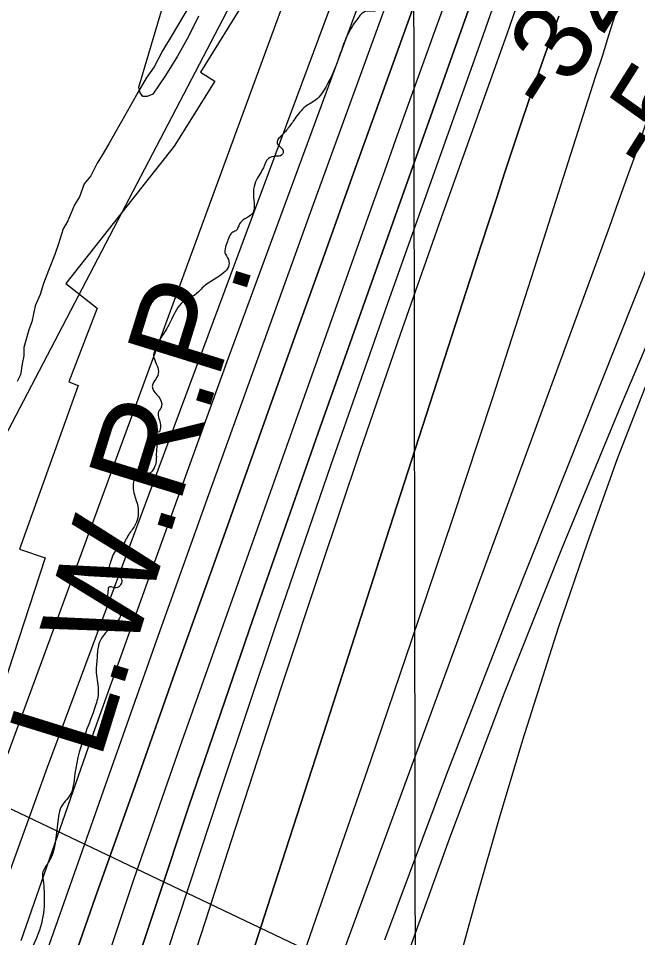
# Model space of a CAD drawing. Extents: x 3324104 to 3361979, y 612876 to 638273.
# Drawn here: x 3333142 to 3333670, y 619975 to 620759 of the extents above; entities that cross this region are included whole.
import ezdxf

# ---------------------------------------------------------------- set-up
doc = ezdxf.new("R2010")
doc.units = 0
for name, color, linetype in [('V-BORW-LINE', 7, 'Continuous'), ('V-GRID-MAJR', 7, 'Continuous'), ('V-RIVR-EDGE', 7, 'Continuous'), ('V-RIVR-RANG', 7, 'Continuous'), ('V-RRAP-RVMT', 7, 'Continuous'), ('V-SITE-VEGE', 7, 'Continuous'), ('V-TOPO-DPTH', 7, 'Continuous'), ('V-TOPO-MAJR', 7, 'Continuous'), ('V-TOPO-MINR', 7, 'Continuous'), ('V-TOPO-WATR', 7, 'Continuous'), ('V-TOPO-WATR-IDEN', 7, 'Continuous')]:
    doc.layers.add(name, color=color, linetype=linetype)

msp = doc.modelspace()

# ---------------------------------------------------------------- linework, layer by layer
at = {"layer": 'V-BORW-LINE'}
msp.add_spline([(3333279.31, 622009.12), (3333231.92, 621951.76), (3333205.11, 621897.16), (3333189.26, 621870.48), (3333179.51, 621841.77), (3333188.99, 621814.26), (3333211.1, 621772.38), (3333204.81, 621737.81), (3333188.63, 621719.97), (3333169, 621718.16), (3333123.21, 621708.41), (3333080.88, 621684.52), (3333055.17, 621653.52), (3333026.61, 621594.88), (3332950.24, 621540.71), (3332914.43, 621496.23), (3332875.47, 621420.15), (3332841.76, 621289.97), (3332823.69, 621156.25), (3332819.5, 621070.99), (3332810.28, 620972.6), (3332794.13, 620819.7), (3332773.59, 620648.76), (3332758.38, 620478.35), (3332763.01, 620333.58), (3332761.44, 620215.25), (3332749.59, 620090.1), (3332736.9, 620020.51), (3332757.48, 619884.42), (3332796.65, 619752.53), (3332836.81, 619685.21), (3332884.12, 619656.72), (3332907.36, 619782.97), (3332924.74, 619872.64), (3332933.46, 619955.31), (3332956.09, 620057.12), (3332961.28, 620162.95), (3332980.06, 620271.9), (3332986.08, 620455.32), (3332994.16, 620598.94), (3332995.81, 620645.82), (3333015.49, 620663.47), (3333033.59, 620670.41), (3333059.26, 620687.46), (3333079.42, 620760.33), (3333099.61, 620886.65), (3333120.36, 621062.97), (3333127.93, 621114.48), (3333147.58, 621275.48), (3333149.44, 621387.58), (3333160.45, 621495.69), (3333147.46, 621529.78), (3333165.68, 621561.99), (3333287.42, 621646.35), (3333352.56, 621666.03), (3333381.9, 621690.89), (3333384.67, 621754.99), (3333383.93, 621811), (3333402.75, 621857.49), (3333424.81, 621899.12), (3333503.16, 622012.37), (3333560.21, 622118.33), (3333589.92, 622173.14), (3333617.46, 622211.23), (3333650.61, 622258.29), (3333640.96, 622317.3), (3333564, 622281.97), (3333518.92, 622253.83), (3333446.06, 622201.36), (3333404.2, 622156.3), (3333335.5, 622066.47), (3333279.31, 622009.12)], degree=3, dxfattribs=at)
at = {"layer": 'V-GRID-MAJR'}
msp.add_spline([(3333482.84, 618266.12), (3333474.02, 624325.46), (3333465.21, 630386.73), (3333456.39, 636448.02), (3333456.39, 636449.93)], degree=3, dxfattribs=at)
at = {"layer": 'V-RIVR-EDGE'}
msp.add_spline([(3334928.97, 623567.85), (3334918.71, 623560.2), (3334914.68, 623556.19), (3334911.74, 623548.52), (3334903.31, 623541.96), (3334897.46, 623537.59), (3334883.89, 623523.37), (3334877.3, 623516.44), (3334875.1, 623512.79), (3334874.72, 623510.23), (3334869.21, 623497.09), (3334851.98, 623477.02), (3334839.87, 623459.87), (3334820.45, 623439.82), (3334813.49, 623432.89), (3334808.72, 623428.15), (3334791.86, 623408.45), (3334776.46, 623388.75), (3334766.19, 623376.71), (3334752.99, 623361.39), (3334747.86, 623355.19), (3334743.82, 623348.25), (3334740.89, 623343.87), (3334732.1, 623337.31), (3334728.8, 623334.4), (3334724.77, 623329.29), (3334712.3, 623315.07), (3334705.34, 623307.04), (3334701.67, 623300.47), (3334697.25, 623288.42), (3334692.47, 623279.29), (3334670.85, 623254.12), (3334652.51, 623232.23), (3334641.14, 623216.91), (3334634.54, 623206.32), (3334620.97, 623189.18), (3334601.16, 623162.54), (3334593.83, 623152.69), (3334582.08, 623132.98), (3334567.04, 623111.08), (3334554.2, 623092.11), (3334532.19, 623061.45), (3334516.05, 623038.46), (3334501.73, 623013.64), (3334486.32, 622989.92), (3334474.96, 622976.42), (3334471.29, 622971.31), (3334468.71, 622964.01), (3334466.11, 622945.37), (3334458.39, 622929.31), (3334449.59, 622916.9), (3334437.49, 622903.41), (3334430.89, 622897.21), (3334429.42, 622893.92), (3334430.51, 622889.17), (3334430.13, 622884.78), (3334422.09, 622884.44), (3334418.06, 622881.52), (3334414.39, 622876.78), (3334408.87, 622862.17), (3334399.7, 622849.03), (3334390.17, 622835.53), (3334378.44, 622826.06), (3334363.06, 622813.66), (3334337.75, 622777.9), (3334331.13, 622762.57), (3334327.81, 622750.15), (3334323.78, 622746.5), (3334319.75, 622741.39), (3334312.78, 622733), (3334306.55, 622727.54), (3334299.94, 622714.39), (3334295.53, 622705.63), (3334291.88, 622705.27), (3334287.48, 622702.36), (3334279.79, 622694.34), (3334261.06, 622661.85), (3334258.85, 622655.27), (3334258.48, 622650.52), (3334256.27, 622646.14), (3334249.67, 622637.39), (3334242.68, 622620.59), (3334233.12, 622595.39), (3334227.97, 622581.88), (3334227.22, 622574.2), (3334223.91, 622567.63), (3334219.88, 622563.62), (3334214.74, 622557.05), (3334213.27, 622550.47), (3334212.51, 622539.88), (3334211.02, 622528.55), (3334205.89, 622523.08), (3334199.67, 622521.63), (3334192.36, 622521.65), (3334181.38, 622517.65), (3334175.51, 622506.7), (3334173.65, 622495.01), (3334174.34, 622480.02), (3334173.22, 622468.69), (3334165.51, 622456.28), (3334156.34, 622440.95), (3334148.28, 622435.49), (3334140.95, 622428.56), (3334132.89, 622422.37), (3334131.79, 622417.62), (3334130.28, 622400.8), (3334129.53, 622392.03), (3334127.69, 622388.75), (3334124.76, 622384.73), (3334120.37, 622384.01), (3334113.42, 622383.67), (3334109.39, 622378.92), (3334105.72, 622372.72), (3334106.08, 622370.89), (3334106.8, 622364.67), (3334104.22, 622358.83), (3334092.86, 622346.07), (3334087.37, 622343.89), (3334077.85, 622335.14), (3334066.49, 622326.03), (3334058.79, 622317.64), (3334055.47, 622304.48), (3334054.73, 622298.64), (3334054.34, 622290.23), (3334052.14, 622286.22), (3334045.55, 622285.14), (3334038.59, 622277.84), (3334027.23, 622264.71), (3334003.75, 622232.6), (3333990.17, 622210.33), (3333969.97, 622172), (3333947.58, 622134.04), (3333931.07, 622108.49), (3333921.53, 622095.36), (3333906.11, 622069.44), (3333885.18, 622030.74), (3333866.11, 622004.11), (3333836.74, 621954.1), (3333808.83, 621904.82), (3333789, 621866.49), (3333773.55, 621825.22), (3333764.35, 621802.58), (3333753.68, 621773.36), (3333750.32, 621746.32), (3333745.51, 621722.57), (3333743.29, 621710.51), (3333742.49, 621684.19), (3333742.81, 621665.91), (3333738.03, 621655.69), (3333731.42, 621640.35), (3333723.35, 621629.41), (3333720.4, 621621.37), (3333716.71, 621607.86), (3333712.63, 621581.55), (3333709.64, 621557.06), (3333708.86, 621537.32), (3333711.36, 621514.29), (3333711.7, 621504.05), (3333710.95, 621494.55), (3333705.08, 621484.33), (3333691.48, 621455.48), (3333683.75, 621436.13), (3333680.79, 621419.32), (3333677.82, 621402.51), (3333676.69, 621386.8), (3333678.84, 621369.25), (3333684.3, 621359), (3333685.75, 621355.34), (3333683.92, 621353.88), (3333681.35, 621349.13), (3333676.95, 621343.66), (3333671.06, 621329.79), (3333664.81, 621313.35), (3333662.97, 621308.24), (3333659.66, 621300.57), (3333655.97, 621286.69), (3333654.86, 621280.11), (3333652.29, 621278.66), (3333646.07, 621275.38), (3333642.77, 621270.27), (3333641.29, 621264.43), (3333642.01, 621259.31), (3333642, 621253.09), (3333639.78, 621245.06), (3333636.12, 621240.68), (3333634.64, 621234.47), (3333623.99, 621213.66), (3333608.54, 621175.68), (3333598.59, 621144.27), (3333594.52, 621124.9), (3333593.41, 621119.42), (3333588.28, 621113.59), (3333583.51, 621106.65), (3333577.64, 621096.43), (3333573.24, 621092.79), (3333568.85, 621090.24), (3333567.74, 621085.49), (3333565.53, 621077.45), (3333558.92, 621067.96), (3333558.55, 621064.68), (3333561.45, 621054.07), (3333560.32, 621041.64), (3333556.27, 621029.59), (3333554.8, 621025.94), (3333558.8, 621018.62), (3333564.63, 621010.19), (3333561.69, 621005.81), (3333557.67, 621003.27), (3333553.63, 620997.06), (3333546.64, 620979.17), (3333540.39, 620964.56), (3333533.77, 620947.4), (3333531.54, 620933.51), (3333527.86, 620925.11), (3333521.25, 620911.97), (3333515.75, 620906.5), (3333510.99, 620902.85), (3333508.41, 620894.82), (3333502.91, 620885.33), (3333500.32, 620874), (3333494.83, 620869.26), (3333490.43, 620866.72), (3333480.53, 620852.48), (3333474.29, 620841.9), (3333459.22, 620811.23), (3333451.52, 620799.92), (3333448.21, 620792.61), (3333444.9, 620782.75), (3333445.25, 620777.27), (3333447.42, 620768.86), (3333445.95, 620765.2), (3333442.66, 620764.85), (3333437.54, 620764.49), (3333431.68, 620759.39), (3333422.14, 620744.06), (3333414.41, 620723.61), (3333401.92, 620696.96), (3333396.42, 620690.02), (3333386.53, 620683.47), (3333377.37, 620672.89), (3333371.86, 620665.23), (3333365.63, 620658.3), (3333363.07, 620655.38), (3333362.69, 620651.36), (3333366.7, 620647.33), (3333367.42, 620644.04), (3333366.32, 620642.21), (3333361.2, 620641.13), (3333354.98, 620639.31), (3333350.58, 620631.28), (3333343.23, 620617.41), (3333342.11, 620608.64), (3333342.82, 620598.77), (3333340.98, 620591.83), (3333334.75, 620587.82), (3333330.35, 620583.45), (3333327.05, 620577.61), (3333323.76, 620575.79), (3333320.82, 620571.04), (3333318.98, 620565.56), (3333317.86, 620558.99), (3333320.77, 620553.13), (3333320.76, 620546.92), (3333316.73, 620541.81), (3333299.52, 620529.79), (3333291.45, 620522.5), (3333285.97, 620519.95), (3333281.94, 620517.04), (3333272.4, 620502.44), (3333265.42, 620489.66), (3333262.48, 620485.28), (3333258.81, 620477.25), (3333256.97, 620471.77), (3333260.96, 620459.33), (3333259.85, 620452.75), (3333255.8, 620444.72), (3333256.89, 620441.43), (3333262.72, 620434.1), (3333263.07, 620426.06), (3333261.24, 620423.51), (3333262.67, 620413.63), (3333262.66, 620408.52), (3333261.92, 620406.32), (3333256.07, 620405.61), (3333253.87, 620402.32), (3333258.98, 620396.83), (3333259.32, 620388.78), (3333259.31, 620385.13), (3333256.73, 620374.17), (3333251.23, 620369.8), (3333245.02, 620369.81), (3333242.09, 620367.99), (3333240.23, 620354.1), (3333243.49, 620342.4), (3333241.62, 620327.42), (3333235.75, 620318.66), (3333229.88, 620309.17), (3333223.29, 620302.97), (3333220.71, 620296.76), (3333219.96, 620286.89), (3333223.97, 620284.69), (3333227.62, 620283.22), (3333229.81, 620279.56), (3333228.33, 620275.18), (3333226.14, 620273.35), (3333218.46, 620273.37), (3333218.09, 620271.55), (3333218.43, 620260.58), (3333225.36, 620253.25), (3333228.64, 620249.59), (3333226.07, 620244.84), (3333215.81, 620234.63), (3333210.3, 620225.51), (3333208.81, 620213.45), (3333208.05, 620200.65), (3333209.83, 620184.57), (3333207.24, 620172.14), (3333199.15, 620150.23), (3333189.92, 620114.79), (3333184.75, 620095.07), (3333180.36, 620089.96), (3333175.2, 620073.89), (3333167.07, 620038.82), (3333162.3, 620030.06), (3333162.65, 620023.84), (3333163.7, 620004.83), (3333159.62, 619981.44), (3333146.75, 619951.87), (3333138.62, 619917.16), (3333131.98, 619891.22), (3333123.86, 619859.8), (3333118.71, 619847.39), (3333115.41, 619841.91), (3333113.14, 619813.41), (3333110.17, 619792.94), (3333103.19, 619781.26), (3333088.16, 619764.12), (3333080.84, 619760.12), (3333074.61, 619752.09), (3333073.5, 619748.07), (3333076.04, 619740.75), (3333075.3, 619736), (3333065.04, 619724.7), (3333062.1, 619720.68), (3333054.4, 619710.83), (3333044.08, 619676.86), (3333031.15, 619622.79), (3333019.73, 619586.27), (3333011.99, 619559.97), (3333004.97, 619532.2), (3333004.23, 619526.35), (3333007.5, 619517.21), (3333006.03, 619513.56), (3333002.35, 619504.79), (3332997.95, 619500.78), (3332994.65, 619495.31), (3332992.4, 619473.74), (3332989.42, 619449.26), (3332987.92, 619433.55), (3332988.61, 619417.83), (3332984.91, 619401.38), (3332980.12, 619386.41), (3332972.42, 619375.1), (3332966.88, 619354.27), (3332958.39, 619318.84), (3332949.88, 619279.01), (3332945.08, 619258.55), (3332945.79, 619249.41), (3332945.03, 619237.72), (3332939.51, 619223.84), (3332931.42, 619204.85), (3332929.91, 619185.85), (3332927.31, 619169.4), (3332922.14, 619148.95), (3332922.49, 619140.17), (3332924.3, 619133.59), (3332920.63, 619127.02), (3332919.51, 619119.34), (3332919.13, 619112.4), (3332916.91, 619099.98), (3332914.32, 619087.92), (3332905.11, 619060.89), (3332898.1, 619033.86), (3332892.56, 619012.3), (3332891.41, 618990.37), (3332890.3, 618984.16), (3332882.96, 618971.75), (3332878.52, 618949.83), (3332874.78, 618918.77), (3332873.6, 618882.22), (3332869.89, 618859.93), (3332865.82, 618842.76), (3332855.9, 618819.38), (3332845.58, 618785.41), (3332838.54, 618748.15), (3332836.99, 618714.15), (3332831.76, 618666.64), (3332832.42, 618639.23), (3332838.58, 618615.82), (3332848.01, 618586.55), (3332849.43, 618569.37), (3332847.54, 618545.97), (3332848.96, 618525.87), (3332853.23, 618480.16), (3332859.29, 618418), (3332861.03, 618383.64), (3332865.68, 618343.05), (3332869.61, 618305.75), (3332871.95, 618265.06)], degree=3, dxfattribs=at)
at = {"layer": 'V-RIVR-RANG'}
msp.add_line((3332596.7, 620341.5), (3333842.42, 619747.72), dxfattribs=at)
at = {"layer": 'V-RRAP-RVMT'}
for p, q in [((3333358.76, 620812.88), (3333296.94, 620712.69)), ((3333296.94, 620712.69), (3333309.24, 620705)), ((3333309.24, 620705), (3333274.49, 620649.69)), ((3333274.49, 620649.69), (3333182.04, 620532.65)), ((3333182.04, 620532.65), (3333208.73, 620511.51)), ((3333208.73, 620511.51), (3333184.77, 620448.75)), ((3333192.78, 620445.67), (3333142.74, 620306.24)), ((3333184.77, 620448.75), (3333192.78, 620445.67)), ((3333142.74, 620306.24), (3333164.46, 620298.67)), ((3333164.46, 620298.67), (3333114.82, 620147.26))]:
    msp.add_line(p, q, dxfattribs=at)
at = {"layer": 'V-SITE-VEGE'}
for p, q in [((3333288.03, 620770.58), (3333272.77, 620744.61)), ((3333272.77, 620744.61), (3333264.45, 620730.95)), ((3333264.45, 620730.95), (3333257.51, 620717.28)), ((3333257.51, 620717.28), (3333250.59, 620707.72)), ((3333250.59, 620707.72), (3333243.65, 620695.42)), ((3333243.65, 620695.42), (3333238.1, 620685.86)), ((3333238.1, 620685.86), (3333218.67, 620651.69)), ((3333218.67, 620651.69), (3333213.13, 620642.12)), ((3333213.13, 620642.12), (3333208.97, 620635.29)), ((3333208.97, 620635.29), (3333203.41, 620624.35)), ((3333197.88, 620617.53), (3333193.69, 620606.58)), ((3333203.41, 620624.35), (3333197.88, 620617.53)), ((3333193.69, 620606.58), (3333189.54, 620599.75)), ((3333189.54, 620599.75), (3333183.96, 620586.07)), ((3333183.96, 620586.07), (3333179.8, 620579.24)), ((3333179.8, 620579.24), (3333175.6, 620565.55)), ((3333175.6, 620565.55), (3333172.8, 620557.34)), ((3333172.8, 620557.34), (3333167.23, 620543.66)), ((3333167.23, 620543.66), (3333163.04, 620532.71)), ((3333163.04, 620532.71), (3333160.23, 620523.13)), ((3333160.23, 620523.13), (3333156.06, 620513.55)), ((3333156.06, 620513.55), (3333153.23, 620499.85)), ((3333153.23, 620499.85), (3333150.44, 620493.01)), ((3333150.44, 620493.01), (3333146.23, 620477.95)), ((3333146.23, 620477.95), (3333146.18, 620471.09)), ((3333146.18, 620471.09), (3333144.77, 620464.24)), ((3333144.77, 620464.24), (3333143.33, 620454.65)), ((3333143.33, 620454.65), (3333140.55, 620449.18))]:
    msp.add_line(p, q, dxfattribs=at)
at = {"layer": 'V-TOPO-DPTH'}
for points in [[(3333713.66, 621614.36), (3333532.53, 621039.06), (3333526.66, 621022.03), (3333520.63, 621005.05), (3333514.36, 620988.16), (3333507.93, 620971.33), (3333501.4, 620954.54), (3333494.87, 620937.75), (3333488.35, 620920.95), (3333481.83, 620904.15), (3333479.59, 620898.35), (3333472.01, 620878.63), (3333464.49, 620858.89), (3333457.08, 620839.11), (3333449.73, 620819.3), (3333319.56, 620465.76), (3333259.89, 620301.6), (3333201.13, 620137.12), (3333143.72, 619972.16)], [(3333173.47, 619912.82), (3333207.27, 620008.82), (3333241.17, 620104.78), (3333275.22, 620200.69), (3333309.38, 620296.56), (3333353, 620418.66), (3333377.82, 620488.04), (3333402.67, 620557.41), (3333427.58, 620626.75), (3333452.53, 620696.09), (3333491.82, 620805.13), (3333497.19, 620819.92), (3333502.62, 620834.68), (3333508.14, 620849.41), (3333513.71, 620864.11), (3333764.04, 621607.46)], [(3333173.47, 619912.82), (3333207.27, 620008.82), (3333241.17, 620104.78), (3333275.22, 620200.69), (3333309.38, 620296.56), (3333353, 620418.66), (3333377.82, 620488.04), (3333402.67, 620557.41), (3333427.58, 620626.75), (3333452.53, 620696.09), (3333491.82, 620805.13), (3333497.19, 620819.92), (3333502.62, 620834.68), (3333508.14, 620849.41), (3333513.71, 620864.11), (3333764.04, 621607.46)], [(3333233.84, 619927.06), (3333287, 620086.96), (3333341.65, 620246.34), (3333397.3, 620405.4), (3333532.83, 620787.03), (3333536.98, 620798.62), (3333541.16, 620810.2), (3333545.39, 620821.76), (3333549.66, 620833.31), (3333551.86, 620839.22), (3333555.05, 620847.81), (3333558.21, 620856.4), (3333561.36, 620865), (3333564.49, 620873.61), (3333567.63, 620882.21), (3333570.79, 620890.81), (3333573.98, 620899.4), (3333577.19, 620907.97), (3333625.77, 621037.01), (3333653.77, 621109.91), (3333682.42, 621182.55), (3333742.28, 621326.79), (3333834.4, 621542.01)], [(3333834.4, 621542.01), (3333742.28, 621326.79), (3333682.42, 621182.55), (3333653.77, 621109.91), (3333625.77, 621037.01), (3333577.19, 620907.97), (3333573.98, 620899.4), (3333570.79, 620890.81), (3333567.63, 620882.21), (3333564.49, 620873.61), (3333561.36, 620865), (3333558.21, 620856.4), (3333555.05, 620847.81), (3333551.86, 620839.22), (3333549.66, 620833.31), (3333545.39, 620821.76), (3333541.16, 620810.2), (3333536.98, 620798.62), (3333532.83, 620787.03), (3333397.3, 620405.4), (3333341.65, 620246.34), (3333287, 620086.96), (3333233.84, 619927.06)], [(3333566.05, 620767.31), (3333558.12, 620745.24), (3333502.33, 620588.75), (3333467.31, 620489.23), (3333432.84, 620389.52), (3333399.2, 620289.52), (3333366.11, 620189.34), (3333345.63, 620126.48), (3333323.23, 620057.58), (3333300.88, 619988.66), (3333278.59, 619919.72)], [(3333566.05, 620767.31), (3333558.12, 620745.24), (3333502.33, 620588.75), (3333467.31, 620489.23), (3333432.84, 620389.52), (3333399.2, 620289.52), (3333366.11, 620189.34), (3333345.63, 620126.48), (3333323.23, 620057.58), (3333300.88, 619988.66), (3333278.59, 619919.72)], [(3333309.52, 619862.79), (3333357.02, 620010.29), (3333404.61, 620157.76), (3333452.28, 620305.2), (3333536.18, 620564.4), (3333542.9, 620585.13), (3333549.63, 620605.86), (3333556.39, 620626.58), (3333563.16, 620647.29), (3333563.41, 620648.07), (3333570.16, 620668.36), (3333577.03, 620688.61), (3333584.07, 620708.8), (3333591.24, 620728.94), (3333602.67, 620760.59)], [(3333309.52, 619862.79), (3333357.02, 620010.29), (3333404.61, 620157.76), (3333452.28, 620305.2), (3333536.18, 620564.4), (3333542.9, 620585.13), (3333549.63, 620605.86), (3333556.39, 620626.58), (3333563.16, 620647.29), (3333563.41, 620648.07), (3333570.16, 620668.36), (3333577.03, 620688.61), (3333584.07, 620708.8), (3333591.24, 620728.94), (3333602.67, 620760.59)], [(3333650.73, 620762.09), (3333645.1, 620744.18), (3333639.43, 620726.29), (3333633.73, 620708.41), (3333579.04, 620537.5), (3333545.62, 620434.3), (3333511.7, 620331.25), (3333477.06, 620228.45), (3333441.92, 620125.82), (3333353.34, 619870.02)], [(3333650.73, 620762.09), (3333645.1, 620744.18), (3333639.43, 620726.29), (3333633.73, 620708.41), (3333579.04, 620537.5), (3333545.62, 620434.3), (3333511.7, 620331.25), (3333477.06, 620228.45), (3333441.92, 620125.82), (3333353.34, 619870.02)]]:
    msp.add_lwpolyline(points, dxfattribs=at)
at = {"layer": 'V-TOPO-MAJR'}
for points in [[(3334261.95, 622295.88), (3333970.42, 621470.67), (3333961.31, 621452.93), (3333690.94, 620715.09), (3333687.23, 620702.77), (3333683.51, 620690.44), (3333679.69, 620678.16), (3333675.75, 620665.91), (3333671.62, 620653.72), (3333667.38, 620641.56), (3333660.93, 620623.52), (3333653.35, 620602.38), (3333645.73, 620581.26), (3333638.06, 620560.16), (3333630.34, 620539.07), (3333406.48, 619929.48)], [(3333668.71, 621638.22), (3333431.42, 621015.4), (3333428.62, 621006.78), (3333403.59, 620939.64), (3333397.05, 620922.68), (3333390.27, 620905.82), (3333383.11, 620889.12), (3333375.7, 620872.53), (3332686.53, 619553.94), (3332685.98, 619548.29), (3332738.27, 618427.48), (3332736.57, 618393.28), (3332731.15, 618264.81)]]:
    msp.add_lwpolyline(points, dxfattribs=at)
at = {"layer": 'V-TOPO-MINR'}
for points in [[(3334216.54, 621784.27), (3333990.42, 621442.73), (3333987.91, 621438.78), (3333985.5, 621434.77), (3333983.23, 621430.68), (3333734.55, 620687.5), (3333723.72, 620661.13), (3333713.04, 620634.69), (3333562.72, 620258.26), (3333507.43, 620115.85), (3333453.97, 619972.78)], [(3333693.6, 621652.86), (3333482.93, 621079.79), (3333477.56, 621063.44), (3333436.13, 620950.76), (3333424.94, 620920.86), (3333413.51, 620891.06), (3333401.74, 620861.4), (3333389.75, 620831.82), (3333066.51, 619952.32)], [(3333738.85, 621619.03), (3333529, 620965.76), (3333515.64, 620931.28), (3333502.7, 620897.7), (3333493, 620872.32), (3333483.4, 620846.9), (3333473.94, 620821.44), (3333464.57, 620795.93), (3333393.17, 620599.86), (3333348.35, 620476.22), (3333303.78, 620352.5), (3333259.58, 620228.64), (3333215.63, 620104.7), (3333056.15, 619652.86)], [(3333694.55, 621617.21), (3333449.45, 620880.67), (3333448.49, 620877.93), (3333447.46, 620875.22), (3333446.6, 620872.98), (3333445.32, 620869.63), (3333444.9, 620868.51), (3333166.33, 620120.01), (3333128.13, 620014.66), (3333091.1, 619908.91)], [(3333713.66, 621614.36), (3333532.53, 621039.06), (3333526.66, 621022.03), (3333520.63, 621005.05), (3333514.36, 620988.16), (3333507.93, 620971.33), (3333501.4, 620954.54), (3333494.87, 620937.75), (3333488.35, 620920.95), (3333481.83, 620904.15), (3333479.59, 620898.35), (3333472.01, 620878.63), (3333464.49, 620858.89), (3333457.08, 620839.11), (3333449.73, 620819.3), (3333319.56, 620465.76), (3333259.89, 620301.6), (3333201.13, 620137.12), (3333143.72, 619972.16)], [(3333802.43, 621595.32), (3333580, 620973.55), (3333525.51, 620828.42), (3333524.26, 620825.06), (3333523.03, 620821.7), (3333521.81, 620818.33), (3333520.61, 620814.95), (3333512.5, 620791.95), (3333507.23, 620777.07), (3333501.94, 620762.21), (3333496.62, 620747.35), (3333491.27, 620732.51), (3333482.67, 620708.73), (3333473.02, 620681.99), (3333463.4, 620655.24), (3333453.83, 620628.48), (3333444.28, 620601.71), (3333279.26, 620137.78), (3333239.88, 620024.31), (3333201.66, 619910.45)], [(3333834.4, 621542.01), (3333742.28, 621326.79), (3333682.42, 621182.55), (3333653.77, 621109.91), (3333625.77, 621037.01), (3333577.19, 620907.97), (3333573.98, 620899.4), (3333570.79, 620890.81), (3333567.63, 620882.21), (3333564.49, 620873.61), (3333561.36, 620865), (3333558.21, 620856.4), (3333555.05, 620847.81), (3333551.86, 620839.22), (3333549.66, 620833.31), (3333545.39, 620821.76), (3333541.16, 620810.2), (3333536.98, 620798.62), (3333532.83, 620787.03), (3333397.3, 620405.4), (3333341.65, 620246.34), (3333287, 620086.96), (3333233.84, 619927.06)], [(3333938.82, 621204.03), (3333931.42, 621186.93), (3333925.46, 621169.44), (3333921.66, 621151.36), (3333919.3, 621132.88), (3333918.67, 621114.13), (3333918.84, 621095.4), (3333920.21, 621076.72), (3333922.39, 621058.08), (3333922.85, 621055.01), (3333923.96, 621035.15), (3333922.7, 621015.67), (3333917.91, 620996.74), (3333910.75, 620978.19), (3333771.16, 620697.14), (3333765.05, 620684.56), (3333759.09, 620671.91), (3333753.36, 620659.15), (3333747.79, 620646.33), (3333655.38, 620428.52), (3333604.9, 620306.28), (3333555.99, 620183.43), (3333509.44, 620059.67), (3333464.46, 619935.3)], [(3333939.95, 620937.02), (3333777.31, 620679.43), (3333773.17, 620672.5), (3333769.26, 620665.45), (3333765.69, 620658.22), (3333762.36, 620650.87), (3333709, 620525.07), (3333680.1, 620454.37), (3333652.45, 620383.21), (3333626.68, 620311.34), (3333602.16, 620239.01), (3333592.57, 620209.45), (3333571.71, 620143.3), (3333551.59, 620076.94), (3333532.56, 620010.26), (3333514.26, 619943.36)], [(3333295.29, 620760.47), (3333286.69, 620743.2), (3333277.43, 620726.31), (3333267.15, 620710.03), (3333256.19, 620694.14), (3333251.47, 620692.12), (3333247.75, 620692.1), (3333245.51, 620695.08), (3333244.28, 620700.07), (3333309.95, 620921.27)], [(3333547.82, 620772.22), (3333537.97, 620744.71), (3333456.57, 620515.65), (3333408.26, 620377.93), (3333360.71, 620239.95), (3333314.29, 620101.59), (3333268.63, 619962.96)], [(3333566.05, 620767.31), (3333558.12, 620745.24), (3333502.33, 620588.75), (3333467.31, 620489.23), (3333432.84, 620389.52), (3333399.2, 620289.52), (3333366.11, 620189.34), (3333345.63, 620126.48), (3333323.23, 620057.58), (3333300.88, 619988.66), (3333278.59, 619919.72)], [(3333602.67, 620760.59), (3333591.24, 620728.94), (3333584.07, 620708.8), (3333577.03, 620688.61), (3333570.16, 620668.36), (3333563.41, 620648.07), (3333563.16, 620647.29), (3333556.39, 620626.58), (3333549.63, 620605.86), (3333542.9, 620585.13), (3333536.18, 620564.4), (3333452.28, 620305.2), (3333404.61, 620157.76), (3333357.02, 620010.29), (3333309.52, 619862.79)], [(3333650.73, 620762.09), (3333645.1, 620744.18), (3333639.43, 620726.29), (3333633.73, 620708.41), (3333579.04, 620537.5), (3333545.62, 620434.3), (3333511.7, 620331.25), (3333477.06, 620228.45), (3333441.92, 620125.82), (3333353.34, 619870.02)]]:
    msp.add_lwpolyline(points, dxfattribs=at)
at = {"layer": 'V-TOPO-WATR'}
msp.add_lwpolyline([(3333764.04, 621607.46), (3333513.71, 620864.11), (3333508.14, 620849.41), (3333502.62, 620834.68), (3333497.19, 620819.92), (3333491.82, 620805.13), (3333452.53, 620696.09), (3333427.58, 620626.75), (3333402.67, 620557.41), (3333377.82, 620488.04), (3333353, 620418.66), (3333309.38, 620296.56), (3333275.22, 620200.69), (3333241.17, 620104.78), (3333207.27, 620008.82), (3333173.47, 619912.82)], dxfattribs=at)

# ---------------------------------------------------------------- texts
at = {"layer": 'V-RIVR-RANG'}
for s, p in [('-32', (3333596.6, 620674.79)), ('-50', (3333682.86, 620624.1))]:
    msp.add_text(s, height=67, rotation=57.73589, dxfattribs=at).set_placement(p)
at = {"layer": 'V-TOPO-WATR-IDEN'}
msp.add_text('L.W.R.P.', height=83, rotation=72.77922, dxfattribs=at).set_placement((3333211.29, 620125.11))

doc.saveas('drawing.dxf')
